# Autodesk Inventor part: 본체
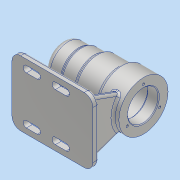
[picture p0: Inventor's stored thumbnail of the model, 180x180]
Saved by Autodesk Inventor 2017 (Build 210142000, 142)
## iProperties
Part Number: 본체
Material: 알루미늄 6061
Document SubType Name: Modeling
Designer: MRC
Density: 2.7 g/cm^3
Appearance: 알루미늄 - 평지
Mass: 691.044 g
Surface Area: 699.056 cm^2
Volume: 255.942 cm^3
Author: MRC
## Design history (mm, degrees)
sketch "스케치1"
  geometry: L1 (0, 0)-(0, 25); L2 (0, 25)-(24, 25); L3 (24, 25)-(24, 27); L4 (24, 27)-(46, 27); L5 (46, 27)-(46, 30); L6 (46, 30)-(80, 30); L7 (80, 30)-(80, 34); L8 (80, 34)-(112, 34); L9 (112, 34)-(112, 21); L10 (112, 21)-(97, 21); L11 (97, 21)-(97, 24); L12 (97, 24)-(43, 24); L13 (43, 24)-(43, 21); L14 (43, 21)-(31, 21); L15 (31, 21)-(31, 17.5); L16 (31, 17.5)-(13, 17.5); L17 (13, 17.5)-(13, 16); L18 (13, 16)-(9, 16); L19 (9, 16)-(9, 10.5); L20 (9, 10.5)-(6, 10.5); L21 (6, 10.5)-(6, 0); L22 (6, 0)-(0, 0)
  constraints: 44 end point, 18 perpendicular, 2 horizontal, 2 vertical, 1 collinear
  dimensions: "d0" = 25 distance between parallel lines of L22 L2; "d1" = 27 distance between parallel lines of L22 L4; "d2" = 30 distance between parallel lines of L22 L6; "d3" = 34 distance between parallel lines of L22 L8; "d4" = 24 distance of L1.end L2.end; "d5" = 46 distance between parallel lines of L1 L5; "d6" = 80 distance between parallel lines of L1 L7; "d7" = 112 distance between parallel lines of L9 L1; "d8" = 15 distance of L9.end L10.end; "d9" = 54 distance of L11.end L12.end; "d10" = 12 distance of L13.end L14.end; "d11" = 18 distance of L15.end L16.end; "d12" = 4 distance of L17.end L18.end; "d13" = 3 distance of L19.end L20.end; "d14" = 24 distance between parallel lines of L22 L12; "d15" = 21 distance between parallel lines of L22 L10; "d16" = 17.5 distance between parallel lines of L22 L16; "d17" = 16 distance between parallel lines of L22 L18; "d18" = 10.5 distance between parallel lines of L22 L20
revolve "회전1" sketch "스케치1" stored, may be unused: angle "d19" = 90 deg
fillet "모깎기1" dims "d20" = 8
node "작업 평면1"
sketch "스케치2"
  geometry: L1 (0, 45)-(-112, 45); L2 (-112, 45)-(-112, -45); L3 (-112, -45)-(0, -45); L4 (0, -45)-(0, 45); L5 (0, 45)-(-112, -45); L6 (-112, 45)-(0, -45); 3 further points
  constraints: 12 end point, 4 midpoint, 2 parallel, 1 horizontal, 1 horizontal alignment, 1 perpendicular
  dimensions: "d22" = 112 distance of L2.end L3.end; "d23" = 90 distance of L3.end L1.start
extrude "돌출1" join sketch "스케치2" distance "d24" = 8; taper "d25" = 0 deg
sketch "스케치3"
  geometry: L1 (112, -45)-(112, 45) reference; L2 (0, 45)-(0, -45) reference; L3 (27, -4)-(104, -4); L4 (104, -4)-(104, 4); L5 (104, 4)-(27, 4); L6 (27, 4)-(27, -4); L7 (27, -4)-(104, 4); L8 (104, -4)-(27, 4); 4 further points
  constraints: 12 end point, 4 midpoint, 2 parallel, 1 horizontal, 1 horizontal alignment, 1 perpendicular
  dimensions: "d26" = 8 distance between parallel lines of L1 L4; "d27" = 77 distance of L4.end L5.end; "d28" = 8 distance of L5.end L3.start
extrude "돌출2" join sketch "스케치3" stored distance "d29" = 8; taper "d30" = 0 deg
sketch "스케치4"
  geometry: L1 (-41, -8)-(-41, 0) reference; L2 (-41, 0)-(0, 0) reference; L3 (0, 0)-(0, 28.236) reference; L4 (8, 28.236)-(8, 0) reference; L5 (8, 0)-(49, 0) reference; L6 (49, 0)-(49, -8) reference; L7 (49, -8)-(-41, -8) reference; L8 (0, 0)-(8, 0) reference; L9 (-19.409, 37.342)-(-33, 0); C1 r 21 at (4, 62) reference; A1 r 34 centre (4, 62) between (8, 28.236) and (0, 28.236) reference; A2 r 34 centre (4, 62) between (0, 28.236) and (8, 28.236) reference
  constraints: 2 end point, 1 point on circle, 1 point on line
  dimensions: "d31" = 8 distance from line of L1 L9.end; "d32" = 110 deg angle of L2 L9
extrude "돌출3" join sketch "스케치4" distance "d33" = 8; taper "d34" = 0 deg
sketch "스케치5"
  geometry: C1 r 21 at (0, 0) reference; 1 further point
  constraints: 1 horizontal alignment
  dimensions: "d35" = 26 distance of C1.centre point (-26, 0)
hole "구멍1" sketch "스케치5" at (-26, 0) diameter "d36" = 3.242; stored, may be unused: countersink angle "d40" = 90 deg, drill point angle "d42" = 118 deg; dims "d37" = 8, "d38" = 4, "d39" = 2, "d41" = 11
sketch "스케치6"
  geometry: L1 (0, 45)-(0, -45) reference; L2 (20, -33)-(35, -33); L3 (24, -25)-(24, 25) reference; L4 (20, -28.5)-(35, -28.5); L5 (35, -37.5)-(20, -37.5); L6 (60, -33)-(75, -33); L7 (60, -28.5)-(75, -28.5); L8 (75, -37.5)-(60, -37.5); A1 r 4.5 centre (20, -33) between (20, -28.5) and (20, -37.5); A2 r 4.5 centre (35, -33) between (35, -37.5) and (35, -28.5); A3 r 4.5 centre (60, -33) between (60, -28.5) and (60, -37.5); A4 r 4.5 centre (75, -33) between (75, -37.5) and (75, -28.5); 3 further points
  constraints: 16 end point, 8 point on circle, 8 tangent, 4 centre point, 2 midpoint, 2 parallel, 1 horizontal, 1 horizontal alignment, 1 perpendicular
  dimensions: "d46" = 20 distance from line of L1 L2.start; "d47" = 15 distance of L2.start L2.end; "d48" = 33 distance from line of point (0, 0) L2; "d49" = 4.5 radius of A1; "d50" = 25 distance of L2.end L6.start; "d51" = 15 distance of L6.start L6.end; "d52" = 4.5 radius of A3
extrude "돌출4" cut sketch "스케치6" distance "d53" = 8; taper "d54" = 0 deg
feature "면 기울기1" dims angle "d55" = 15 deg
fillet "모깎기2" dims "d56" = 12
fillet "모깎기3" dims "d57" = 3
fillet "모깎기4" dims "d58" = 3
fillet "모깎기5" dims "d59" = 3
fillet "모깎기6" dims "d60" = 3
fillet "모깎기7" dims "d61" = 3
fillet "모깎기8" dims "d62" = 0.3
sketch "스케치7"
  geometry: L1 (0, 33)-(0, -33) reference; 3 further points
  constraints: 1 horizontal alignment, 1 midpoint, 1 other
  dimensions: "d63" = 12 distance from line of L1 point (12, 0)
feature "엠보싱1" sketch "스케치7" dims "d0" = 25, "d1" = 27, "d2" = 30, "d3" = 34, "d4" = 24, "d5" = 46, "d6" = 80, "d7" = 112, "d8" = 15, "d9" = 54, "d10" = 12, "d11" = 18, "d12" = 4, "d13" = 3, "d14" = 24, "d15" = 21, "d16" = 17.5, "d17" = 16, "d18" = 10.5, "d64" = 0.5, "d65" = 0
chamfer "모따기1" distance "d66" = 1; stored, may be unused: second distance "d67" = 2, angle "d68" = 45 deg
node "솔리드1"
mirror "미러1"
pattern_circular "원형 패턴1" dims angle "d44" = 360 deg
mirror "미러2"
node "절단 모서리 투영1"
